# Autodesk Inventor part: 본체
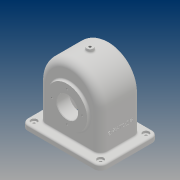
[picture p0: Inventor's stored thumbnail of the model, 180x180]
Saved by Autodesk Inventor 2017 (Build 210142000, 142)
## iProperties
Part Number: 본체
Material: 일반
Document SubType Name: Modeling
Designer: 20
Density: 1 g/cm^3
Appearance: 기본값
Author: 20
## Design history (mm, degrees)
sketch "스케치4"
  geometry: L1 (58, 13)-(58, -65); L2 (-58, 13)-(-58, -65); L3 (58, -65)-(-58, -65); A1 r 58 centre (0, 13) between (58, 13) and (-58, 13); 1 further point
  constraints: 6 end point, 2 point on circle, 2 tangent, 2 vertical, 1 centre point, 1 horizontal, 1 vertical alignment
  dimensions: "d10" = 116 diameter of A1; "d11" = 13 distance of point (0, 0) A1.centre; "d12" = 78 distance from line of L3 A1.centre
extrude "돌출2" new body sketch "스케치4" stored distance "d13" = 77; taper "d14" = 0 deg
sketch "스케치7"
  geometry: C1 r 38 at (0, 0); 1 further point
  constraints: 1 centre point, 1 coincident
  dimensions: "d22" = 76 diameter of C1
extrude "돌출3" join sketch "스케치7" distance "d23" = 5; taper "d24" = 0 deg
sketch "스케치8"
  geometry: C1 r 38 at (0, 0); 1 further point
  constraints: 1 centre point, 1 coincident
  dimensions: "d25" = 76 diameter of C1
extrude "돌출4" join sketch "스케치8" distance "d26" = 10; taper "d27" = 0 deg
sketch "스케치10"
  geometry: L1 (133, -93.5)-(-17, -93.5); L2 (-17, -93.5)-(-17, 16.5); L3 (-17, 16.5)-(133, 16.5); L4 (133, 16.5)-(133, -93.5); L5 (133, -93.5)-(-17, 16.5); L6 (-17, -93.5)-(133, 16.5); 1 further point
  constraints: 12 end point, 2 midpoint, 2 parallel, 1 horizontal, 1 perpendicular
  dimensions: "d29" = 150 distance of L2.end L3.end; "d30" = 110 distance of L1.end L2.end
extrude "돌출5" join sketch "스케치10" distance "d31" = 10; taper "d32" = 0 deg
sketch "스케치12"
  geometry: L1 (52, 13)-(52, -65); L2 (-52, 13)-(-52, -65); L3 (52, -65)-(-52, -65); L4 (-75, -65)-(75, -65) reference; A1 r 52 centre (0, 13) between (52, 13) and (-52, 13); A2 r 58 centre (0, 13) between (58, 13) and (-58, 13) reference; 1 further point
  constraints: 6 end point, 2 point on circle, 2 tangent, 2 vertical, 1 centre point, 1 collinear, 1 concentric, 1 horizontal
  dimensions: "d33" = 104 diameter of A1
extrude "돌출6" cut sketch "스케치12" stored distance "d34" = 67; taper "d35" = 0 deg
sketch "스케치13"
  geometry: C1 r 28 at (0, 0); 1 further point
  constraints: 1 centre point, 1 coincident
  dimensions: "d36" = 56 diameter of C1
extrude "돌출7" join sketch "스케치13" distance "d37" = 14; taper "d38" = 0 deg
feature "면 기울기1" dims angle "d39" = 40 deg
sketch "스케치14"
  geometry: C1 r 20 at (0, 0); 1 further point
  constraints: 1 centre point, 1 coincident
  dimensions: "d40" = 40 diameter of C1
extrude "돌출8" cut sketch "스케치14" stored distance "d41" = 14; taper "d42" = 0 deg
node "작업 평면2"
sketch "스케치16"
  geometry: L1 (150, 110)-(150, 0) reference; L2 (150, 0)-(0, 0) reference; C1 r 6 at (75, 55); 1 further point
  constraints: 1 centre point
  dimensions: "d44" = 12 diameter of C1; "d45" = 75 distance from line of L1 C1.centre; "d46" = 55 distance from line of L2 C1.centre
extrude "돌출9" join sketch "스케치16" stored distance "d47" = 14; taper "d48" = 0 deg
sketch "스케치17"
  geometry: 2 further points
  constraints: 1 vertical alignment
  dimensions: "d49" = 29 distance of point (0, 0) point (0, 29)
hole "구멍1" sketch "스케치17" at (0, 29) diameter "d50" = 3.242; stored, may be unused: countersink angle "d54" = 90 deg, drill point angle "d56" = 118 deg; dims "d51" = 8, "d52" = 4, "d53" = 2, "d55" = 10
sketch "스케치18"
  geometry: 2 further points
  constraints: 1 vertical alignment
  dimensions: "d60" = 29 distance of point (0, 0) point (0, -29)
hole "구멍2" sketch "스케치18" at (0, -29) diameter "d61" = 3.242; stored, may be unused: countersink angle "d65" = 90 deg, drill point angle "d67" = 118 deg; dims "d62" = 8, "d63" = 4, "d64" = 2, "d66" = 10
fillet "모깎기1" dims "d71" = 12
fillet "모깎기2" dims "d72" = 3
sketch "스케치19"
  geometry: L1 (-133, 4.5)-(-133, -81.5) reference; L2 (-121, -93.5)-(5, -93.5) reference; 2 further points
  dimensions: "d73" = 12 distance from line of L1 point (-121, -81.5); "d74" = 12 distance from line of L2 point (-121, -81.5)
hole "구멍3" sketch "스케치19" at (-121, -81.5) diameter "d75" = 5; stored, may be unused: countersink angle "d79" = 90 deg, drill point angle "d81" = 118 deg; dims "d76" = 8, "d77" = 12, "d78" = 4, "d80" = 10
fillet "모깎기3" dims "d88" = 13
hole "구멍4" diameter "d92" = 4.459; stored, may be unused: countersink angle "d96" = 90 deg, drill point angle "d98" = 118 deg; dims "d90" = 10, "d91" = 10, "d93" = 10, "d94" = 12, "d95" = 4, "d97" = 12.8
fillet "모깎기5" dims "d99" = 8
fillet "모깎기6" dims "d100" = 3
fillet "모깎기7" dims "d101" = 3
node "작업 평면3"
sketch "스케치20"
  geometry: L1 (78, -17.5)-(78, 68.5) reference; L2 (0, -13)-(65, -13) reference; 2 further points
  constraints: 1 other
  dimensions: "d103" = 40 distance from line of L1 point (38, 25.5); "d104" = 38.5 distance from line of L2 point (38, 25.5)
feature "엠보싱1" sketch "스케치20" dims "d10" = 116, "d11" = 13, "d12" = 78, "d29" = 150, "d30" = 110, "d105" = 0.5, "d106" = 0
feature "면 기울기2" dims angle "d107" = 5 deg
fillet "모깎기8" dims "d108" = 3
chamfer "모따기1" distance "d109" = 1; stored, may be unused: second distance "d110" = 2, angle "d111" = 45 deg
node "솔리드2"
pattern_circular "원형 패턴1" dims angle "d58" = 360 deg
pattern_circular "원형 패턴2" dims angle "d69" = 360 deg
pattern_linear "직사각형 패턴1" dims "d84" = 86, "d87" = 126
other parameters: "d43" = -142
